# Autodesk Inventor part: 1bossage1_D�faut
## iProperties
Created: 2011-01
Part Number: 1bossage1_D�faut
Document SubType Name: Modeling
Designer: eric
Density: 1 g/cm^3
Mass: 2.5631 g
Surface Area: 27.1515 cm^2
Volume: 2.5631 cm^3
Author: eric
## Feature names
1. Base1
